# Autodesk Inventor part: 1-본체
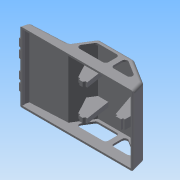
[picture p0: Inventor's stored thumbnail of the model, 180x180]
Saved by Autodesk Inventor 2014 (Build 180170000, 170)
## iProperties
Created: 2015-05
Part Number: 1-본체
Material: Generic
Document SubType Name: Modeling
Designer: Administrator
Density: 1 g/cm^3
Appearance: Default
Author: Administrator
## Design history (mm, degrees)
sketch "스케치1"
  geometry: L1 (0, 0)-(122, 0); L2 (54.409, 31)-(93, 31); L3 (1.144, 9)-(42, 11.141); L4 (42, 11.141)-(54.409, 31); L5 (122, 0)-(122, 1); L6 (122, 1)-(123, 1); L7 (123, 1)-(119.378, 14.517); L8 (93, 31)-(119.378, 14.517); L9 (119.378, 14.517)-(125.007, 11); L10 (0, 0)-(0, 1); L11 (0, 1)-(-1, 1); L12 (-1, 1)-(1.144, 9)
  constraints: 24 end point, 6 perpendicular, 1 horizontal, 1 parallel
  dimensions: "d0" = 122 distance of L1.start L1.end; "d46" = 42 horizontal distance of L3.end L1.start; "d47" = 125 deg angle of L4 L3; "d59" = 3 deg angle of L1 L3; "d63" = 31 vertical distance of L2.end L1.end; "d67" = 1 distance of L1.end L5.end; "d68" = 1 distance of L5.end L6.end; "d69" = 105 deg angle of L7 L1; "d70" = 30 horizontal distance of L6.end L2.end; "d73" = 20 vertical distance of L2.end L9.end; "d84" = 1 distance of L10.end L11.end; "d85" = 1 distance of L1.start L10.end; "d86" = 9 vertical distance of L3.start L1.start; "d87" = 105 deg angle of L1 L12
extrude "돌출1" new body sketch "스케치1" distance "d49" = 76; taper "d50" = 0 deg
feature "쉘1" dims "d83" = 2
sketch "스케치2"
  geometry: L1 (93, 31)-(54.409, 31) reference; L2 (54.409, 31)-(42, 11.141) reference; L3 (58.844, 26)-(78.808, 26); L4 (81.808, 23)-(81.808, 14); L5 (78.808, 11)-(53.22, 11); L6 (50.676, 15.59)-(56.299, 24.59); L7 (87.571, 23)-(87.571, 14); L8 (90.571, 11)-(105.109, 11); L9 (106.699, 16.544)-(91.566, 26); L10 (90.571, 26)-(91.566, 26); L11 (123, 1)-(119.378, 14.517) reference; L12 (119.378, 14.517)-(93, 31) reference; A1 r 3 centre (58.844, 23) between (58.844, 26) and (56.299, 24.59); A2 r 3 centre (53.22, 14) between (50.676, 15.59) and (53.22, 11); A3 r 3 centre (78.808, 14) between (78.808, 11) and (81.808, 14); A4 r 3 centre (78.808, 23) between (81.808, 23) and (78.808, 26); A5 r 3 centre (90.571, 23) between (90.571, 26) and (87.571, 23); A6 r 3 centre (105.109, 14) between (105.109, 11) and (106.699, 16.544); A7 r 3 centre (90.571, 14) between (87.571, 14) and (90.571, 11); 6 further points
  constraints: 16 end point, 14 point on circle, 14 tangent, 12 point on line, 7 centre point, 6 equal radius, 5 parallel, 3 perpendicular
  dimensions: "d52" = 5 distance between parallel lines of L1 L3; "d53" = 5 distance between parallel lines of L1 L10; "d54" = 28 distance of point (87.571, 11) point (115.571, 11); "d55" = 5 distance between parallel lines of L6 L2; "d56" = 34 distance of point (81.808, 11) point (47.808, 11); "d57" = 15 vertical distance of point (47.808, 11) point (57.181, 26); "d58" = 15 distance of point (87.571, 26) point (87.571, 11); "d74" = 5 distance between parallel lines of L12 L9; "d75" = 3 radius of A1
extrude "돌출2" cut sketch "스케치2" stored distance "d76" = 76; taper "d77" = 0 deg
node "작업 평면1"
sketch "스케치3"
  geometry: L1 (10.456, 51)-(30.456, 51); L2 (30.456, 51)-(30.456, 25); L3 (30.456, 25)-(10.456, 25); L4 (10.456, 25)-(10.456, 51); L5 (10.456, 51)-(30.456, 25); L6 (30.456, 51)-(10.456, 25); L7 (0, 76)-(0, 0) reference; L8 (40.912, 76)-(0, 76) reference; 6 further points
  constraints: 12 end point, 6 midpoint, 2 parallel, 1 horizontal, 1 horizontal alignment, 1 perpendicular, 1 vertical alignment
  dimensions: "d79" = 20 distance of L2.end L3.end; "d80" = 26 distance of L1.end L2.end
extrude "돌출3" join sketch "스케치3" stored distance "d81" = 76; taper "d82" = 0 deg
node "작업 평면2"
sketch "스케치4"
  geometry: L1 (0, 8.282)-(76, 8.282) reference; A1 r 4 centre (28, 0) between (32, 0) and (24, 0); A2 r 4 centre (48, 0) between (52, 0) and (44, 0); A3 r 4 centre (59, 0) between (63, 0) and (55, 0); A4 r 4 centre (17, 0) between (21, 0) and (13, 0); 4 further points
  constraints: 8 point on circle, 4 centre point, 3 equal radius, 14 other
  dimensions: "d89" = 4 radius of A4; "d90" = 11 distance of A1.centre A4.centre; "d91" = 11 distance of A3.centre A2.centre; "d92" = 20 distance of A2.centre A1.centre; "d93" = 10 distance of point (38, 0) A1.centre
extrude "돌출4" join sketch "스케치4" stored distance "d94" = 76; taper "d95" = 0 deg
sketch "스케치5"
  geometry: L1 (38.591, 0)-(38.591, -76) reference; L2 (68.591, 0)-(68.591, -76) reference; 3 further points
  constraints: 1 horizontal alignment, 1 midpoint, 1 other
  dimensions: "d96" = 50 horizontal distance of L2.start point (18.591, -38)
feature "엠보싱1" sketch "스케치5" dims "d97" = 0.5, "d98" = 0
node "작업 평면3"
sketch "스케치6"
  geometry: L1 (117.65, 13.239)-(92.427, 29) reference; L2 (92.427, 29)-(55.518, 29) reference; L3 (120.394, 3)-(117.65, 13.239) reference; L4 (0, 0)-(122, 0) reference; L5 (120, 0)-(120, 3) reference; L6 (120, 3)-(120.394, 3) reference; L7 (105.109, 11)-(90.571, 11) reference; L8 (91.566, 26)-(106.699, 16.544) reference; L9 (87.571, 14)-(87.571, 23) reference; L10 (92.427, 29)-(101.699, 2); L11 (101.699, 2)-(103.699, 2); L12 (111.969, 16.789)-(111.699, 2); L13 (111.699, 2)-(109.699, 2); L14 (103.699, 2)-(103.769, 0); L15 (109.699, 2)-(109.629, 0); L16 (106.699, 0)-(106.699, 16.544); L17 (92.427, 29)-(111.969, 16.789); A1 r 3 centre (105.109, 14) between (105.109, 11) and (106.699, 16.544) reference; A2 r 3 centre (90.571, 23) between (90.571, 26) and (87.571, 23) reference; A3 r 3 centre (90.571, 14) between (87.571, 14) and (90.571, 11) reference
  constraints: 16 end point, 4 point on line, 3 collinear, 2 perpendicular, 1 parallel
  dimensions: "d102" = 6 distance of L13.end L11.end; "d103" = 2 deg angle of L16 L14; "d105" = 2 deg angle of L16 L15; "d106" = 10 distance of L12.end L10.end; "d109" = 2 vertical distance of L15.end L12.end; "d110" = 20 deg angle of L12 L10; "d111" = 5 horizontal distance of L12.end L16.start
extrude "돌출5" join sketch "스케치6" stored distance "d112" = 10; taper "d113" = 0 deg
node "작업 평면4"
sketch "스케치7"
  geometry: L1 (92.427, 29)-(55.518, 29) reference; L2 (55.518, 29)-(43.144, 9.198) reference; L3 (0, 0)-(122, 0) reference; L4 (78.808, 11)-(53.22, 11) reference; L5 (50.676, 15.59)-(56.299, 24.59) reference; L6 (58.844, 26)-(78.808, 26) reference; L7 (81.808, 23)-(81.808, 14) reference; L8 (50.587, 21.109)-(61.014, 2); L9 (61.014, 2)-(62.922, 2); L10 (62.922, 2)-(64.014, 0); L11 (66.738, 29)-(70.831, 2); L12 (70.831, 2)-(68.922, 2); L13 (68.922, 2)-(67.831, 0); L14 (66.014, 11)-(66.014, 0); A1 r 3 centre (53.22, 14) between (50.676, 15.59) and (53.22, 11) reference; A2 r 3 centre (58.844, 23) between (58.844, 26) and (56.299, 24.59) reference; A3 r 3 centre (78.808, 23) between (81.808, 23) and (78.808, 26) reference; A4 r 3 centre (78.808, 14) between (78.808, 11) and (81.808, 14) reference
  constraints: 14 end point, 5 point on line, 2 equal length, 2 parallel, 1 collinear, 1 midpoint, 1 perpendicular
  dimensions: "d115" = 20 deg angle of L11 L8; "d116" = 2 distance from line of L3 L8.end; "d117" = 2 distance from line of L3 L11.end; "d118" = 5 horizontal distance of L14.end L8.end; "d119" = 28.6199 deg angle of L14 L10; "d120" = 6 distance of L12.end L9.end; "d121" = 2 distance of L14.end L10.end
extrude "돌출6" join sketch "스케치7" stored distance "d122" = 5; taper "d123" = 0 deg
node "작업 평면5"
node "작업 평면6"
fillet "모깎기1" dims "d144" = 3
fillet "모깎기2" dims "d145" = 3
fillet "모깎기3" dims "d146" = 3
fillet "모깎기4" dims "d147" = 3
node "솔리드1"
mirror "대칭1"
other parameters: "d78" = 5, "d88" = 2, "d114" = -21
